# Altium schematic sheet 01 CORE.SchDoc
size 513 x 386 mm
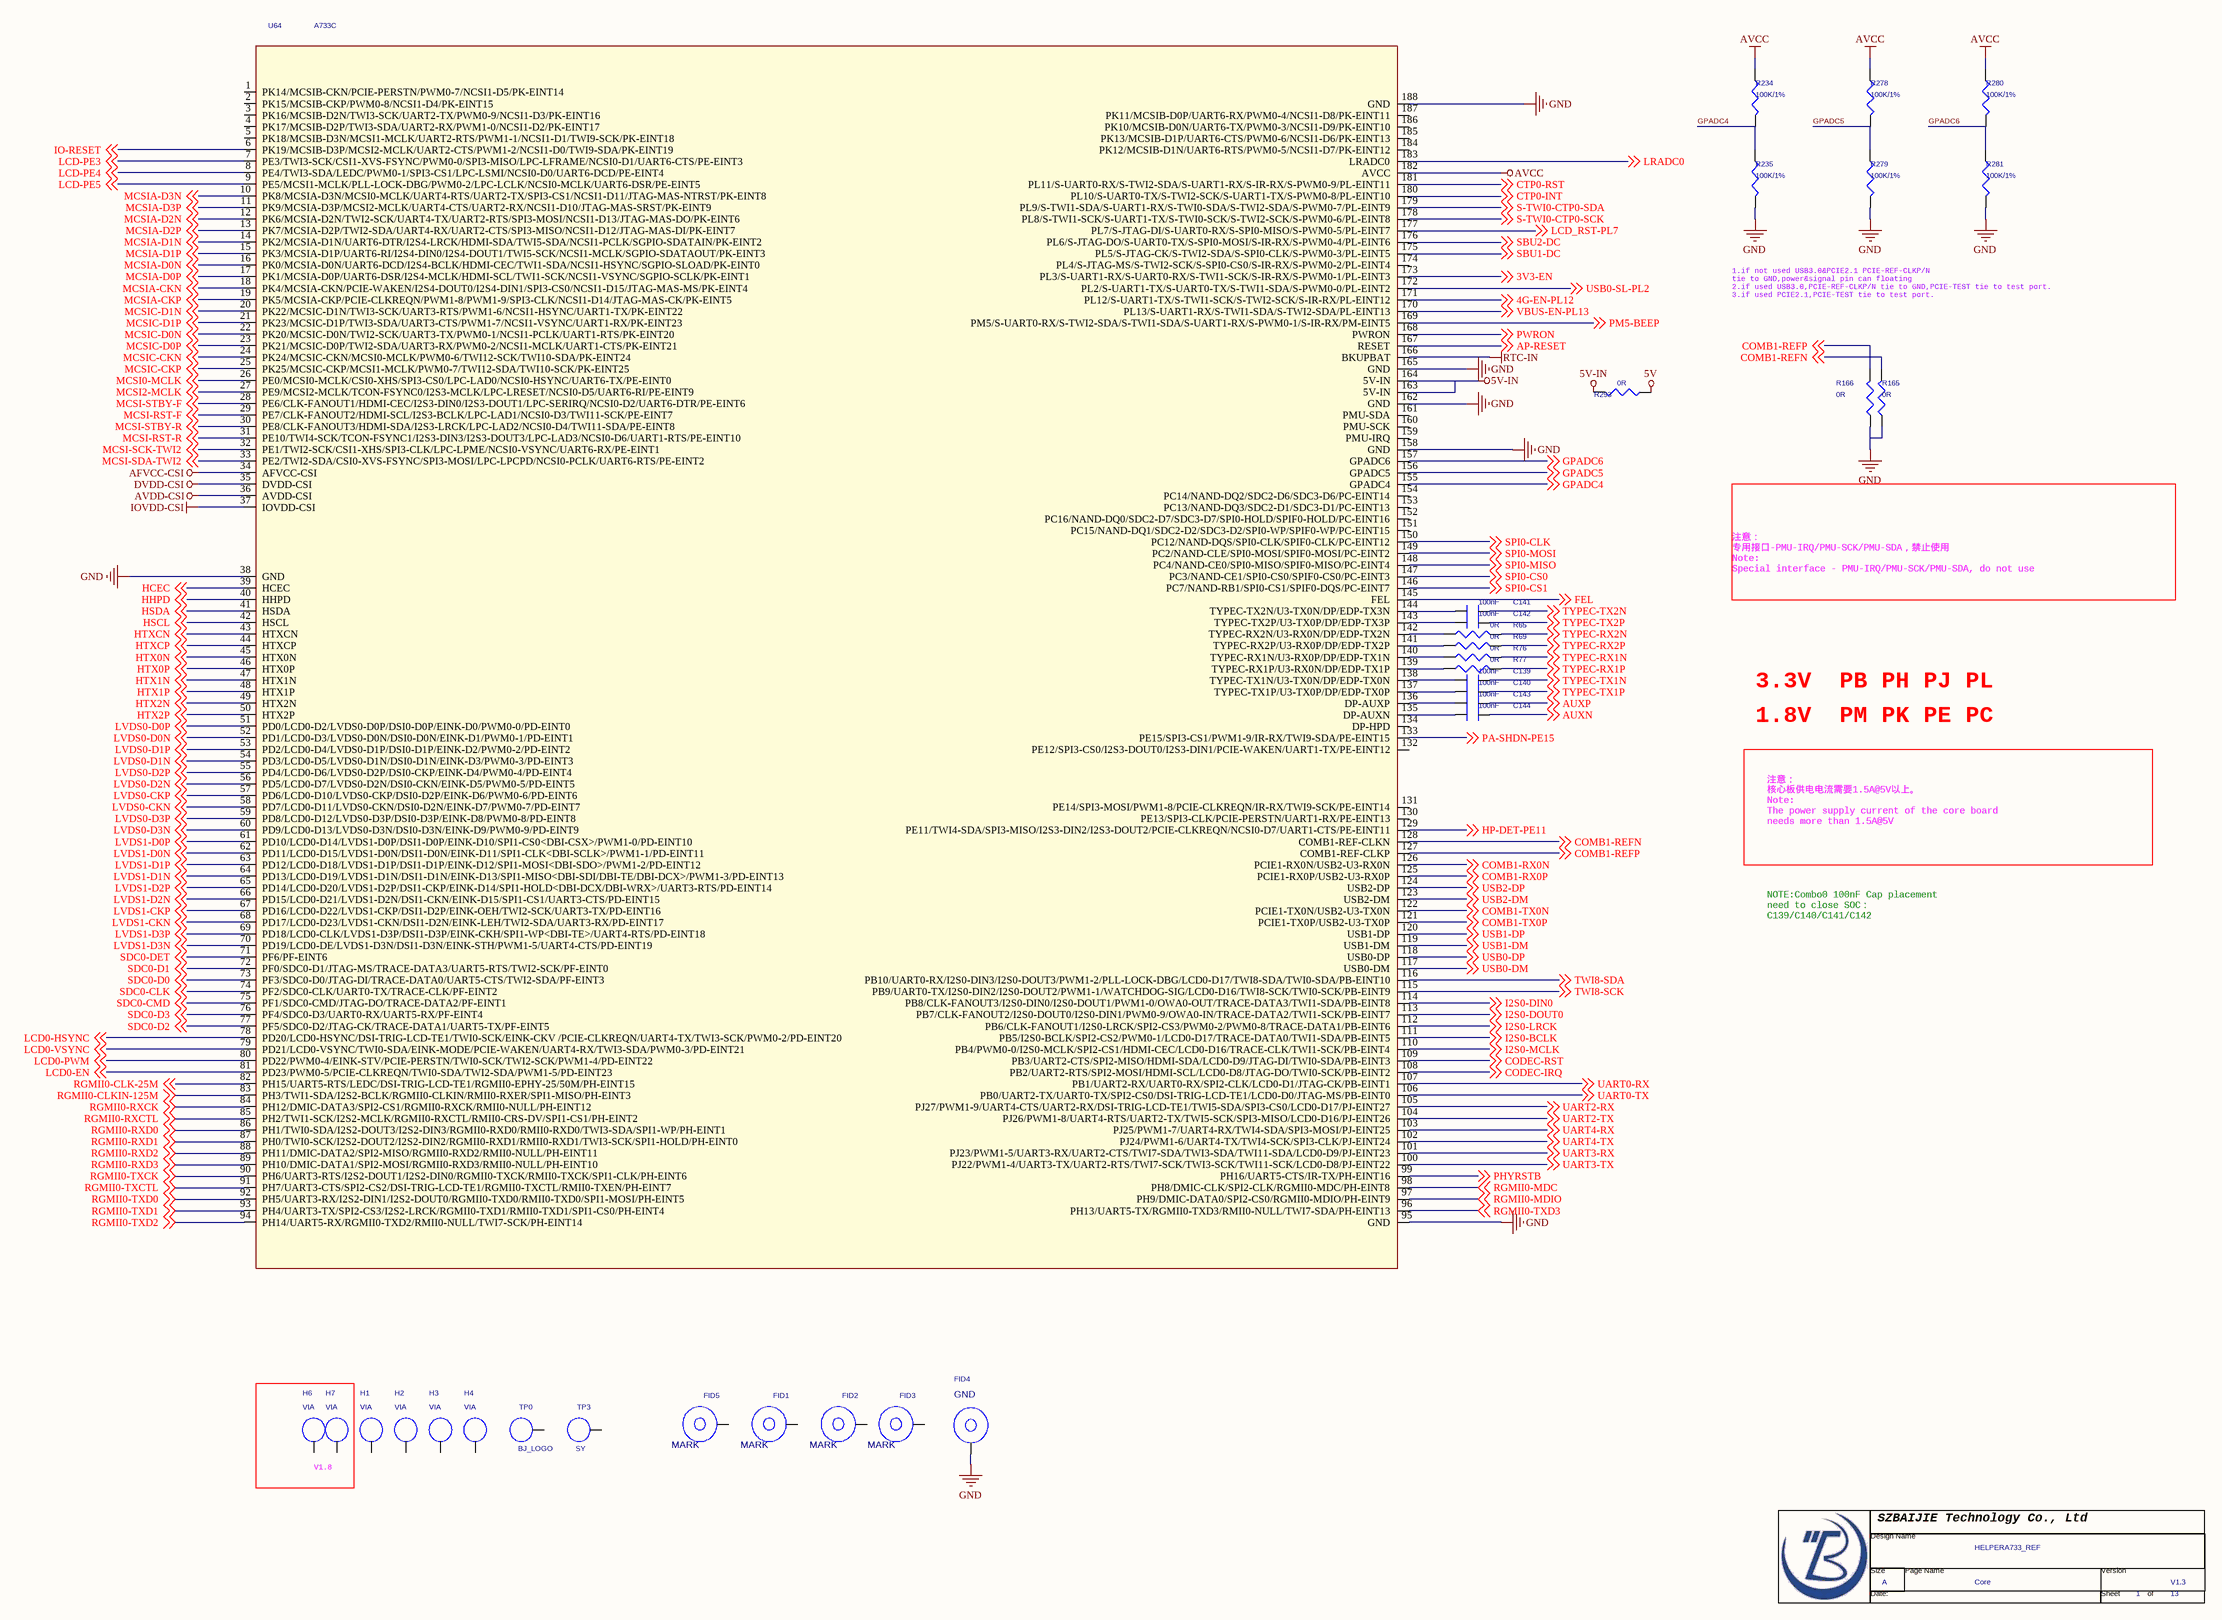
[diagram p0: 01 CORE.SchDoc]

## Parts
*  Page Count: 13  Page Number: 1  Page Size: A  Title: HELPERA733_REF  RevCode: V1.3  Doc: Core  (hidden comment: TitleBlock0-BJ)  (graphical)
C139  100nF  [C0402]
C140  100nF  [C0402]
C141  100nF  [C0402]
C142  100nF  [C0402]
C143  100nF  [C0402]
C144  100nF  [C0402]
FID1  MARK  [FIDICALMARK]
FID2  MARK  [FIDICALMARK]
FID3  MARK  [FIDICALMARK]
FID4  GND  [FIDICALMARK]
FID5  MARK  [FIDICALMARK]
H1  VIA  [DV]
H2  VIA  [DV]
H3  VIA  [DV]
H4  VIA  [DV]
H6  VIA  [DV]
H7  VIA  [DV]
R65  0R  [R0402]
R69  0R  [R0402]
R76  0R  [R0402]
R77  0R  [R0402]
R165  0R  [R0402]
R166  0R  [R0402]
R234  100K/1%  [0805]
R235  100K/1%  [0805]
R278  100K/1%  [0805]
R279  100K/1%  [0805]
R280  100K/1%  [0805]
R281  100K/1%  [0805]
R293  0R  [R0805]
TP0  BJ_LOGO  [BJ_LOGO]
TP3  SY  [6X6]
U64  A733C  [HELPERA733D-1]

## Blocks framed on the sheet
V1.8: H6 H7

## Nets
5V: R293.1
5V-IN: R293.2 U64.163(5V-IN) U64.164(5V-IN)
AFVCC-CSI: U64.34(AFVCC-CSI)
AVCC: R234.1 R278.1 R280.1 U64.182(AVCC)
AVDD-CSI: U64.36(AVDD-CSI)
DVDD-CSI: U64.35(DVDD-CSI)
GND: FID4.1(TP) R165.1 R166.1 R235.2 R279.2 R281.2 U64.38(GND) U64.95(GND) U64.158(GND) U64.162(GND) U64.165(GND) U64.188(GND)
IOVDD-CSI: U64.37(IOVDD-CSI)
RTC-IN: U64.166(BKUPBAT)
3V3-EN: U64.173(PL3/S-UART1-RX/S-UART0-RX/S-TWI1-SCK/S-IR-RX/S-PWM0-1/PL-EINT3) ; off-sheet 3V3-EN
4G-EN-PL12: U64.171(PL12/S-UART1-TX/S-TWI1-SCK/S-TWI2-SCK/S-IR-RX/PL-EINT12) ; off-sheet 4G-EN-PL12
AP-RESET: U64.167(RESET) ; off-sheet AP-RESET
AUXN: C144.2 ; off-sheet AUXN
AUXP: C143.2 ; off-sheet AUXP
CODEC-IRQ: U64.108(PB2/UART2-RTS/SPI2-MOSI/HDMI-SCL/LCD0-D8/JTAG-DO/TWI0-SCK/PB-EINT2) ; off-sheet CODEC-IRQ
CODEC-RST: U64.109(PB3/UART2-CTS/SPI2-MISO/HDMI-SDA/LCD0-D9/JTAG-DI/TWI0-SDA/PB-EINT3) ; off-sheet CODEC-RST
COMB1-REFN: R165.2 U64.128(COMB1-REF-CLKN) ; off-sheet COMB1-REFN
COMB1-REFP: R166.2 U64.127(COMB1-REF-CLKP) ; off-sheet COMB1-REFP
COMB1-RX0N: U64.126(PCIE1-RX0N/USB2-U3-RX0N) ; off-sheet COMB1-RX0N
COMB1-RX0P: U64.125(PCIE1-RX0P/USB2-U3-RX0P) ; off-sheet COMB1-RX0P
COMB1-TX0N: U64.122(PCIE1-TX0N/USB2-U3-TX0N) ; off-sheet COMB1-TX0N
COMB1-TX0P: U64.121(PCIE1-TX0P/USB2-U3-TX0P) ; off-sheet COMB1-TX0P
CTP0-INT: U64.180(PL10/S-UART0-TX/S-TWI2-SCK/S-UART1-TX/S-PWM0-8/PL-EINT10) ; off-sheet CTP0-INT
CTP0-RST: U64.181(PL11/S-UART0-RX/S-TWI2-SDA/S-UART1-RX/S-IR-RX/S-PWM0-9/PL-EINT11) ; off-sheet CTP0-RST
FEL: U64.145(FEL) ; off-sheet FEL
GPADC4: R234.2 R235.1 U64.155(GPADC4) ; off-sheet GPADC4
GPADC5: R278.2 R279.1 U64.156(GPADC5) ; off-sheet GPADC5
GPADC6: R280.2 R281.1 U64.157(GPADC6) ; off-sheet GPADC6
HCEC: U64.39(HCEC) ; off-sheet HCEC
HHPD: U64.40(HHPD) ; off-sheet HHPD
HP-DET-PE11: U64.129(PE11/TWI4-SDA/SPI3-MISO/I2S3-DIN2/I2S3-DOUT2/PCIE-CLKREQN/NCSI0-D7/UART1-CTS/PE-EINT11) ; off-sheet HP-DET-PE11
HSCL: U64.42(HSCL) ; off-sheet HSCL
HSDA: U64.41(HSDA) ; off-sheet HSDA
HTX0N: U64.45(HTX0N) ; off-sheet HTX0N
HTX0P: U64.46(HTX0P) ; off-sheet HTX0P
HTX1N: U64.47(HTX1N) ; off-sheet HTX1N
HTX1P: U64.48(HTX1P) ; off-sheet HTX1P
HTX2N: U64.49(HTX2N) ; off-sheet HTX2N
HTX2P: U64.50(HTX2P) ; off-sheet HTX2P
HTXCN: U64.43(HTXCN) ; off-sheet HTXCN
HTXCP: U64.44(HTXCP) ; off-sheet HTXCP
I2S0-BCLK: U64.111(PB5/I2S0-BCLK/SPI2-CS2/PWM0-1/LCD0-D17/TRACE-DATA0/TWI1-SDA/PB-EINT5) ; off-sheet I2S0-BCLK
I2S0-DIN0: U64.114(PB8/CLK-FANOUT3/I2S0-DIN0/I2S0-DOUT1/PWM1-0/OWA0-OUT/TRACE-DATA3/TWI1-SDA/PB-EINT8) ; off-sheet I2S0-DIN0
I2S0-DOUT0: U64.113(PB7/CLK-FANOUT2/I2S0-DOUT0/I2S0-DIN1/PWM0-9/OWA0-IN/TRACE-DATA2/TWI1-SCK/PB-EINT7) ; off-sheet I2S0-DOUT0
I2S0-LRCK: U64.112(PB6/CLK-FANOUT1/I2S0-LRCK/SPI2-CS3/PWM0-2/PWM0-8/TRACE-DATA1/PB-EINT6) ; off-sheet I2S0-LRCK
I2S0-MCLK: U64.110(PB4/PWM0-0/I2S0-MCLK/SPI2-CS1/HDMI-CEC/LCD0-D16/TRACE-CLK/TWI1-SCK/PB-EINT4) ; off-sheet I2S0-MCLK
IO-RESET: U64.6(PK19/MCSIB-D3P/MCSI2-MCLK/UART2-CTS/PWM1-2/NCSI1-D0/TWI9-SDA/PK-EINT19) ; off-sheet IO-RESET
LCD0-EN: U64.81(PD23/PWM0-5/PCIE-CLKREQN/TWI0-SDA/TWI2-SDA/PWM1-5/PD-EINT23) ; off-sheet LCD0-EN
LCD0-HSYNC: U64.78(PD20/LCD0-HSYNC/DSI-TRIG-LCD-TE1/TWI0-SCK/EINK-CKV_/PCIE-CLKREQN/UART4-TX/TWI3-SCK/PWM0-2/PD-EINT20) ; off-sheet LCD0-HSYNC
LCD0-PWM: U64.80(PD22/PWM0-4/EINK-STV/PCIE-PERSTN/TWI0-SCK/TWI2-SCK/PWM1-4/PD-EINT22) ; off-sheet LCD0-PWM
LCD0-VSYNC: U64.79(PD21/LCD0-VSYNC/TWI0-SDA/EINK-MODE/PCIE-WAKEN/UART4-RX/TWI3-SDA/PWM0-3/PD-EINT21) ; off-sheet LCD0-VSYNC
LCD-PE3: U64.7(PE3/TWI3-SCK/CSI1-XVS-FSYNC/PWM0-0/SPI3-MISO/LPC-LFRAME/NCSI0-D1/UART6-CTS/PE-EINT3) ; off-sheet LCD-PE3
LCD-PE4: U64.8(PE4/TWI3-SDA/LEDC/PWM0-1/SPI3-CS1/LPC-LSMI/NCSI0-D0/UART6-DCD/PE-EINT4) ; off-sheet LCD-PE4
LCD-PE5: U64.9(PE5/MCSI1-MCLK/PLL-LOCK-DBG/PWM0-2/LPC-LCLK/NCSI0-MCLK/UART6-DSR/PE-EINT5) ; off-sheet LCD-PE5
LCD_RST-PL7: U64.177(PL7/S-JTAG-DI/S-UART0-RX/S-SPI0-MISO/S-PWM0-5/PL-EINT7) ; off-sheet LCD_RST-PL7
LRADC0: U64.183(LRADC0) ; off-sheet LRADC0
LVDS0-CKN: U64.58(PD7/LCD0-D11/LVDS0-CKN/DSI0-D2N/EINK-D7/PWM0-7/PD-EINT7) ; off-sheet LVDS0-CKN
LVDS0-CKP: U64.57(PD6/LCD0-D10/LVDS0-CKP/DSI0-D2P/EINK-D6/PWM0-6/PD-EINT6) ; off-sheet LVDS0-CKP
LVDS0-D0N: U64.52(PD1/LCD0-D3/LVDS0-D0N/DSI0-D0N/EINK-D1/PWM0-1/PD-EINT1) ; off-sheet LVDS0-D0N
LVDS0-D0P: U64.51(PD0/LCD0-D2/LVDS0-D0P/DSI0-D0P/EINK-D0/PWM0-0/PD-EINT0) ; off-sheet LVDS0-D0P
LVDS0-D1N: U64.54(PD3/LCD0-D5/LVDS0-D1N/DSI0-D1N/EINK-D3/PWM0-3/PD-EINT3) ; off-sheet LVDS0-D1N
LVDS0-D1P: U64.53(PD2/LCD0-D4/LVDS0-D1P/DSI0-D1P/EINK-D2/PWM0-2/PD-EINT2) ; off-sheet LVDS0-D1P
LVDS0-D2N: U64.56(PD5/LCD0-D7/LVDS0-D2N/DSI0-CKN/EINK-D5/PWM0-5/PD-EINT5) ; off-sheet LVDS0-D2N
LVDS0-D2P: U64.55(PD4/LCD0-D6/LVDS0-D2P/DSI0-CKP/EINK-D4/PWM0-4/PD-EINT4) ; off-sheet LVDS0-D2P
LVDS0-D3N: U64.60(PD9/LCD0-D13/LVDS0-D3N/DSI0-D3N/EINK-D9/PWM0-9/PD-EINT9) ; off-sheet LVDS0-D3N
LVDS0-D3P: U64.59(PD8/LCD0-D12/LVDS0-D3P/DSI0-D3P/EINK-D8/PWM0-8/PD-EINT8) ; off-sheet LVDS0-D3P
LVDS1-CKN: U64.68(PD17/LCD0-D23/LVDS1-CKN/DSI1-D2N/EINK-LEH/TWI2-SDA/UART3-RX/PD-EINT17) ; off-sheet LVDS1-CKN
LVDS1-CKP: U64.67(PD16/LCD0-D22/LVDS1-CKP/DSI1-D2P/EINK-OEH/TWI2-SCK/UART3-TX/PD-EINT16) ; off-sheet LVDS1-CKP
LVDS1-D0N: U64.62(PD11/LCD0-D15/LVDS1-D0N/DSI1-D0N/EINK-D11/SPI1-CLK<DBI-SCLK>/PWM1-1/PD-EINT11) ; off-sheet LVDS1-D0N
LVDS1-D0P: U64.61(PD10/LCD0-D14/LVDS1-D0P/DSI1-D0P/EINK-D10/SPI1-CS0<DBI-CSX>/PWM1-0/PD-EINT10) ; off-sheet LVDS1-D0P
LVDS1-D1N: U64.64(PD13/LCD0-D19/LVDS1-D1N/DSI1-D1N/EINK-D13/SPI1-MISO<DBI-SDI/DBI-TE/DBI-DCX>/PWM1-3/PD-EINT13) ; off-sheet LVDS1-D1N
LVDS1-D1P: U64.63(PD12/LCD0-D18/LVDS1-D1P/DSI1-D1P/EINK-D12/SPI1-MOSI<DBI-SDO>/PWM1-2/PD-EINT12) ; off-sheet LVDS1-D1P
LVDS1-D2N: U64.66(PD15/LCD0-D21/LVDS1-D2N/DSI1-CKN/EINK-D15/SPI1-CS1/UART3-CTS/PD-EINT15) ; off-sheet LVDS1-D2N
LVDS1-D2P: U64.65(PD14/LCD0-D20/LVDS1-D2P/DSI1-CKP/EINK-D14/SPI1-HOLD<DBI-DCX/DBI-WRX>/UART3-RTS/PD-EINT14) ; off-sheet LVDS1-D2P
LVDS1-D3N: U64.70(PD19/LCD0-DE/LVDS1-D3N/DSI1-D3N/EINK-STH/PWM1-5/UART4-CTS/PD-EINT19) ; off-sheet LVDS1-D3N
LVDS1-D3P: U64.69(PD18/LCD0-CLK/LVDS1-D3P/DSI1-D3P/EINK-CKH/SPI1-WP<DBI-TE>/UART4-RTS/PD-EINT18) ; off-sheet LVDS1-D3P
MCSI0-MCLK: U64.26(PE0/MCSI0-MCLK/CSI0-XHS/SPI3-CS0/LPC-LAD0/NCSI0-HSYNC/UART6-TX/PE-EINT0) ; off-sheet MCSI0-MCLK
MCSI2-MCLK: U64.27(PE9/MCSI2-MCLK/TCON-FSYNC0/I2S3-MCLK/LPC-LRESET/NCSI0-D5/UART6-RI/PE-EINT9) ; off-sheet MCSI2-MCLK
MCSI-RST-F: U64.29(PE7/CLK-FANOUT2/HDMI-SCL/I2S3-BCLK/LPC-LAD1/NCSI0-D3/TWI11-SCK/PE-EINT7) ; off-sheet MCSI-RST-F
MCSI-RST-R: U64.31(PE10/TWI4-SCK/TCON-FSYNC1/I2S3-DIN3/I2S3-DOUT3/LPC-LAD3/NCSI0-D6/UART1-RTS/PE-EINT10) ; off-sheet MCSI-RST-R
MCSI-SCK-TWI2: U64.32(PE1/TWI2-SCK/CSI1-XHS/SPI3-CLK/LPC-LPME/NCSI0-VSYNC/UART6-RX/PE-EINT1) ; off-sheet MCSI-SCK-TWI2
MCSI-SDA-TWI2: U64.33(PE2/TWI2-SDA/CSI0-XVS-FSYNC/SPI3-MOSI/LPC-LPCPD/NCSI0-PCLK/UART6-RTS/PE-EINT2) ; off-sheet MCSI-SDA-TWI2
MCSI-STBY-F: U64.28(PE6/CLK-FANOUT1/HDMI-CEC/I2S3-DIN0/I2S3-DOUT1/LPC-SERIRQ/NCSI0-D2/UART6-DTR/PE-EINT6) ; off-sheet MCSI-STBY-F
MCSI-STBY-R: U64.30(PE8/CLK-FANOUT3/HDMI-SDA/I2S3-LRCK/LPC-LAD2/NCSI0-D4/TWI11-SDA/PE-EINT8) ; off-sheet MCSI-STBY-R
MCSIA-CKN: U64.18(PK4/MCSIA-CKN/PCIE-WAKEN/I2S4-DOUT0/I2S4-DIN1/SPI3-CS0/NCSI1-D15/JTAG-MAS-MS/PK-EINT4) ; off-sheet MCSIA-CKN
MCSIA-CKP: U64.19(PK5/MCSIA-CKP/PCIE-CLKREQN/PWM1-8/PWM1-9/SPI3-CLK/NCSI1-D14/JTAG-MAS-CK/PK-EINT5) ; off-sheet MCSIA-CKP
MCSIA-D0N: U64.16(PK0/MCSIA-D0N/UART6-DCD/I2S4-BCLK/HDMI-CEC/TWI1-SDA/NCSI1-HSYNC/SGPIO-SLOAD/PK-EINT0) ; off-sheet MCSIA-D0N
MCSIA-D0P: U64.17(PK1/MCSIA-D0P/UART6-DSR/I2S4-MCLK/HDMI-SCL/TWI1-SCK/NCSI1-VSYNC/SGPIO-SCLK/PK-EINT1) ; off-sheet MCSIA-D0P
MCSIA-D1N: U64.14(PK2/MCSIA-D1N/UART6-DTR/I2S4-LRCK/HDMI-SDA/TWI5-SDA/NCSI1-PCLK/SGPIO-SDATAIN/PK-EINT2) ; off-sheet MCSIA-D1N
MCSIA-D1P: U64.15(PK3/MCSIA-D1P/UART6-RI/I2S4-DIN0/I2S4-DOUT1/TWI5-SCK/NCSI1-MCLK/SGPIO-SDATAOUT/PK-EINT3) ; off-sheet MCSIA-D1P
MCSIA-D2N: U64.12(PK6/MCSIA-D2N/TWI2-SCK/UART4-TX/UART2-RTS/SPI3-MOSI/NCSI1-D13/JTAG-MAS-DO/PK-EINT6) ; off-sheet MCSIA-D2N
MCSIA-D2P: U64.13(PK7/MCSIA-D2P/TWI2-SDA/UART4-RX/UART2-CTS/SPI3-MISO/NCSI1-D12/JTAG-MAS-DI/PK-EINT7) ; off-sheet MCSIA-D2P
MCSIA-D3N: U64.10(PK8/MCSIA-D3N/MCSI0-MCLK/UART4-RTS/UART2-TX/SPI3-CS1/NCSI1-D11/JTAG-MAS-NTRST/PK-EINT8) ; off-sheet MCSIA-D3N
MCSIA-D3P: U64.11(PK9/MCSIA-D3P/MCSI2-MCLK/UART4-CTS/UART2-RX/NCSI1-D10/JTAG-MAS-SRST/PK-EINT9) ; off-sheet MCSIA-D3P
MCSIC-CKN: U64.24(PK24/MCSIC-CKN/MCSI0-MCLK/PWM0-6/TWI12-SCK/TWI10-SDA/PK-EINT24) ; off-sheet MCSIC-CKN
MCSIC-CKP: U64.25(PK25/MCSIC-CKP/MCSI1-MCLK/PWM0-7/TWI12-SDA/TWI10-SCK/PK-EINT25) ; off-sheet MCSIC-CKP
MCSIC-D0N: U64.22(PK20/MCSIC-D0N/TWI2-SCK/UART3-TX/PWM0-1/NCSI1-PCLK/UART1-RTS/PK-EINT20) ; off-sheet MCSIC-D0N
MCSIC-D0P: U64.23(PK21/MCSIC-D0P/TWI2-SDA/UART3-RX/PWM0-2/NCSI1-MCLK/UART1-CTS/PK-EINT21) ; off-sheet MCSIC-D0P
MCSIC-D1N: U64.20(PK22/MCSIC-D1N/TWI3-SCK/UART3-RTS/PWM1-6/NCSI1-HSYNC/UART1-TX/PK-EINT22) ; off-sheet MCSIC-D1N
MCSIC-D1P: U64.21(PK23/MCSIC-D1P/TWI3-SDA/UART3-CTS/PWM1-7/NCSI1-VSYNC/UART1-RX/PK-EINT23) ; off-sheet MCSIC-D1P
PA-SHDN-PE15: U64.133(PE15/SPI3-CS1/PWM1-9/IR-RX/TWI9-SDA/PE-EINT15) ; off-sheet PA-SHDN-PE15
PHYRSTB: U64.99(PH16/UART5-CTS/IR-TX/PH-EINT16) ; off-sheet PHYRSTB
PM5-BEEP: U64.169(PM5/S-UART0-RX/S-TWI2-SDA/S-TWI1-SDA/S-UART1-RX/S-PWM0-1/S-IR-RX/PM-EINT5) ; off-sheet PM5-BEEP
PWRON: U64.168(PWRON) ; off-sheet PWRON
RGMII0-CLK-25M: U64.82(PH15/UART5-RTS/LEDC/DSI-TRIG-LCD-TE1/RGMII0-EPHY-25/50M/PH-EINT15) ; off-sheet RGMII0-CLK-25M
RGMII0-CLKIN-125M: U64.83(PH3/TWI1-SDA/I2S2-BCLK/RGMII0-CLKIN/RMII0-RXER/SPI1-MISO/PH-EINT3) ; off-sheet RGMII0-CLKIN-125M
RGMII0-MDC: U64.98(PH8/DMIC-CLK/SPI2-CLK/RGMII0-MDC/PH-EINT8) ; off-sheet RGMII0-MDC
RGMII0-MDIO: U64.97(PH9/DMIC-DATA0/SPI2-CS0/RGMII0-MDIO/PH-EINT9) ; off-sheet RGMII0-MDIO
RGMII0-RXCK: U64.84(PH12/DMIC-DATA3/SPI2-CS1/RGMII0-RXCK/RMII0-NULL/PH-EINT12) ; off-sheet RGMII0-RXCK
RGMII0-RXCTL: U64.85(PH2/TWI1-SCK/I2S2-MCLK/RGMII0-RXCTL/RMII0-CRS-DV/SPI1-CS1/PH-EINT2) ; off-sheet RGMII0-RXCTL
RGMII0-RXD0: U64.86(PH1/TWI0-SDA/I2S2-DOUT3/I2S2-DIN3/RGMII0-RXD0/RMII0-RXD0/TWI3-SDA/SPI1-WP/PH-EINT1) ; off-sheet RGMII0-RXD0
RGMII0-RXD1: U64.87(PH0/TWI0-SCK/I2S2-DOUT2/I2S2-DIN2/RGMII0-RXD1/RMII0-RXD1/TWI3-SCK/SPI1-HOLD/PH-EINT0) ; off-sheet RGMII0-RXD1
RGMII0-RXD2: U64.88(PH11/DMIC-DATA2/SPI2-MISO/RGMII0-RXD2/RMII0-NULL/PH-EINT11) ; off-sheet RGMII0-RXD2
RGMII0-RXD3: U64.89(PH10/DMIC-DATA1/SPI2-MOSI/RGMII0-RXD3/RMII0-NULL/PH-EINT10) ; off-sheet RGMII0-RXD3
RGMII0-TXCK: U64.90(PH6/UART3-RTS/I2S2-DOUT1/I2S2-DIN0/RGMII0-TXCK/RMII0-TXCK/SPI1-CLK/PH-EINT6) ; off-sheet RGMII0-TXCK
RGMII0-TXCTL: U64.91(PH7/UART3-CTS/SPI2-CS2/DSI-TRIG-LCD-TE1/RGMII0-TXCTL/RMII0-TXEN/PH-EINT7) ; off-sheet RGMII0-TXCTL
RGMII0-TXD0: U64.92(PH5/UART3-RX/I2S2-DIN1/I2S2-DOUT0/RGMII0-TXD0/RMII0-TXD0/SPI1-MOSI/PH-EINT5) ; off-sheet RGMII0-TXD0
RGMII0-TXD1: U64.93(PH4/UART3-TX/SPI2-CS3/I2S2-LRCK/RGMII0-TXD1/RMII0-TXD1/SPI1-CS0/PH-EINT4) ; off-sheet RGMII0-TXD1
RGMII0-TXD2: U64.94(PH14/UART5-RX/RGMII0-TXD2/RMII0-NULL/TWI7-SCK/PH-EINT14) ; off-sheet RGMII0-TXD2
RGMII0-TXD3: U64.96(PH13/UART5-TX/RGMII0-TXD3/RMII0-NULL/TWI7-SDA/PH-EINT13) ; off-sheet RGMII0-TXD3
S-TWI0-CTP0-SCK: U64.178(PL8/S-TWI1-SCK/S-UART1-TX/S-TWI0-SCK/S-TWI2-SCK/S-PWM0-6/PL-EINT8) ; off-sheet S-TWI0-CTP0-SCK
S-TWI0-CTP0-SDA: U64.179(PL9/S-TWI1-SDA/S-UART1-RX/S-TWI0-SDA/S-TWI2-SDA/S-PWM0-7/PL-EINT9) ; off-sheet S-TWI0-CTP0-SDA
SBU1-DC: U64.175(PL5/S-JTAG-CK/S-TWI2-SDA/S-SPI0-CLK/S-PWM0-3/PL-EINT5) ; off-sheet SBU1-DC
SBU2-DC: U64.176(PL6/S-JTAG-DO/S-UART0-TX/S-SPI0-MOSI/S-IR-RX/S-PWM0-4/PL-EINT6) ; off-sheet SBU2-DC
SDC0-CLK: U64.74(PF2/SDC0-CLK/UART0-TX/TRACE-CLK/PF-EINT2) ; off-sheet SDC0-CLK
SDC0-CMD: U64.75(PF1/SDC0-CMD/JTAG-DO/TRACE-DATA2/PF-EINT1) ; off-sheet SDC0-CMD
SDC0-D0: U64.73(PF3/SDC0-D0/JTAG-DI/TRACE-DATA0/UART5-CTS/TWI2-SDA/PF-EINT3) ; off-sheet SDC0-D0
SDC0-D1: U64.72(PF0/SDC0-D1/JTAG-MS/TRACE-DATA3/UART5-RTS/TWI2-SCK/PF-EINT0) ; off-sheet SDC0-D1
SDC0-D2: U64.77(PF5/SDC0-D2/JTAG-CK/TRACE-DATA1/UART5-TX/PF-EINT5) ; off-sheet SDC0-D2
SDC0-D3: U64.76(PF4/SDC0-D3/UART0-RX/UART5-RX/PF-EINT4) ; off-sheet SDC0-D3
SDC0-DET: U64.71(PF6/PF-EINT6) ; off-sheet SDC0-DET
SPI0-CLK: U64.150(PC12/NAND-DQS/SPI0-CLK/SPIF0-CLK/PC-EINT12) ; off-sheet SPI0-CLK
SPI0-CS0: U64.147(PC3/NAND-CE1/SPI0-CS0/SPIF0-CS0/PC-EINT3) ; off-sheet SPI0-CS0
SPI0-CS1: U64.146(PC7/NAND-RB1/SPI0-CS1/SPIF0-DQS/PC-EINT7) ; off-sheet SPI0-CS1
SPI0-MISO: U64.148(PC4/NAND-CE0/SPI0-MISO/SPIF0-MISO/PC-EINT4) ; off-sheet SPI0-MISO
SPI0-MOSI: U64.149(PC2/NAND-CLE/SPI0-MOSI/SPIF0-MOSI/PC-EINT2) ; off-sheet SPI0-MOSI
TWI8-SCK: U64.115(PB9/UART0-TX/I2S0-DIN2/I2S0-DOUT2/PWM1-1/WATCHDOG-SIG/LCD0-D16/TWI8-SCK/TWI0-SCK/PB-EINT9) ; off-sheet TWI8-SCK
TWI8-SDA: U64.116(PB10/UART0-RX/I2S0-DIN3/I2S0-DOUT3/PWM1-2/PLL-LOCK-DBG/LCD0-D17/TWI8-SDA/TWI0-SDA/PB-EINT10) ; off-sheet TWI8-SDA
TYPEC-RX1N: R76.2 ; off-sheet TYPEC-RX1N
TYPEC-RX1P: R77.2 ; off-sheet TYPEC-RX1P
TYPEC-RX2N: R65.2 ; off-sheet TYPEC-RX2N
TYPEC-RX2P: R69.2 ; off-sheet TYPEC-RX2P
TYPEC-TX1N: C139.2 ; off-sheet TYPEC-TX1N
TYPEC-TX1P: C140.2 ; off-sheet TYPEC-TX1P
TYPEC-TX2N: C141.2 ; off-sheet TYPEC-TX2N
TYPEC-TX2P: C142.2 ; off-sheet TYPEC-TX2P
UART0-RX: U64.107(PB1/UART2-RX/UART0-RX/SPI2-CLK/LCD0-D1/JTAG-CK/PB-EINT1) ; off-sheet UART0-RX
UART0-TX: U64.106(PB0/UART2-TX/UART0-TX/SPI2-CS0/DSI-TRIG-LCD-TE1/LCD0-D0/JTAG-MS/PB-EINT0) ; off-sheet UART0-TX
UART2-RX: U64.105(PJ27/PWM1-9/UART4-CTS/UART2-RX/DSI-TRIG-LCD-TE1/TWI5-SDA/SPI3-CS0/LCD0-D17/PJ-EINT27) ; off-sheet UART2-RX
UART2-TX: U64.104(PJ26/PWM1-8/UART4-RTS/UART2-TX/TWI5-SCK/SPI3-MISO/LCD0-D16/PJ-EINT26) ; off-sheet UART2-TX
UART3-RX: U64.101(PJ23/PWM1-5/UART3-RX/UART2-CTS/TWI7-SDA/TWI3-SDA/TWI11-SDA/LCD0-D9/PJ-EINT23) ; off-sheet UART3-RX
UART3-TX: U64.100(PJ22/PWM1-4/UART3-TX/UART2-RTS/TWI7-SCK/TWI3-SCK/TWI11-SCK/LCD0-D8/PJ-EINT22) ; off-sheet UART3-TX
UART4-RX: U64.103(PJ25/PWM1-7/UART4-RX/TWI4-SDA/SPI3-MOSI/PJ-EINT25) ; off-sheet UART4-RX
UART4-TX: U64.102(PJ24/PWM1-6/UART4-TX/TWI4-SCK/SPI3-CLK/PJ-EINT24) ; off-sheet UART4-TX
USB0-DM: U64.117(USB0-DM) ; off-sheet USB0-DM
USB0-DP: U64.118(USB0-DP) ; off-sheet USB0-DP
USB0-SL-PL2: U64.172(PL2/S-UART1-TX/S-UART0-TX/S-TWI1-SDA/S-PWM0-0/PL-EINT2) ; off-sheet USB0-SL-PL2
USB1-DM: U64.119(USB1-DM) ; off-sheet USB1-DM
USB1-DP: U64.120(USB1-DP) ; off-sheet USB1-DP
USB2-DM: U64.123(USB2-DM) ; off-sheet USB2-DM
USB2-DP: U64.124(USB2-DP) ; off-sheet USB2-DP
VBUS-EN-PL13: U64.170(PL13/S-UART1-RX/S-TWI1-SDA/S-TWI2-SDA/PL-EINT13) ; off-sheet VBUS-EN-PL13
NetC139_1: C139.1 U64.138(TYPEC-TX1N/U3-TX0N/DP/EDP-TX0N)
NetC140_1: C140.1 U64.137(TYPEC-TX1P/U3-TX0P/DP/EDP-TX0P)
NetC141_1: C141.1 U64.144(TYPEC-TX2N/U3-TX0N/DP/EDP-TX3N)
NetC142_1: C142.1 U64.143(TYPEC-TX2P/U3-TX0P/DP/EDP-TX3P)
NetC143_1: C143.1 U64.136(DP-AUXP)
NetC144_1: C144.1 U64.135(DP-AUXN)
NetR65_1: R65.1 U64.142(TYPEC-RX2N/U3-RX0N/DP/EDP-TX2N)
NetR69_1: R69.1 U64.141(TYPEC-RX2P/U3-RX0P/DP/EDP-TX2P)
NetR76_1: R76.1 U64.140(TYPEC-RX1N/U3-RX0P/DP/EDP-TX1N)
NetR77_1: R77.1 U64.139(TYPEC-RX1P/U3-RX0N/DP/EDP-TX1P)

Not connected (* = marked no-connect by the designer): FID1 1(TP); FID2 1(TP); FID3 1(TP); FID5 1(TP); H1 1(TP); H2 1(TP); H3 1(TP); H4 1(TP); H6 1(TP); H7 1(TP); TP0 1(TP); TP3 1(TP); U64 1(PK14/MCSIB-CKN/PCIE-PERSTN/PWM0-7/NCSI1-D5/PK-EINT14) 2(PK15/MCSIB-CKP/PWM0-8/NCSI1-D4/PK-EINT15) 3(PK16/MCSIB-D2N/TWI3-SCK/UART2-TX/PWM0-9/NCSI1-D3/PK-EINT16) 4(PK17/MCSIB-D2P/TWI3-SDA/UART2-RX/PWM1-0/NCSI1-D2/PK-EINT17) 5(PK18/MCSIB-D3N/MCSI1-MCLK/UART2-RTS/PWM1-1/NCSI1-D1/TWI9-SCK/PK-EINT18) 130(PE13/SPI3-CLK/PCIE-PERSTN/UART1-RX/PE-EINT13) 131(PE14/SPI3-MOSI/PWM1-8/PCIE-CLKREQN/IR-RX/TWI9-SCK/PE-EINT14) 132(PE12/SPI3-CS0/I2S3-DOUT0/I2S3-DIN1/PCIE-WAKEN/UART1-TX/PE-EINT12) 134(DP-HPD) 151(PC15/NAND-DQ1/SDC2-D2/SDC3-D2/SPI0-WP/SPIF0-WP/PC-EINT15) 152(PC16/NAND-DQ0/SDC2-D7/SDC3-D7/SPI0-HOLD/SPIF0-HOLD/PC-EINT16) 153(PC13/NAND-DQ3/SDC2-D1/SDC3-D1/PC-EINT13) 154(PC14/NAND-DQ2/SDC2-D6/SDC3-D6/PC-EINT14) 159(PMU-IRQ) 160(PMU-SCK) 161(PMU-SDA) 174(PL4/S-JTAG-MS/S-TWI2-SCK/S-SPI0-CS0/S-IR-RX/S-PWM0-2/PL-EINT4) 184(PK12/MCSIB-D1N/UART6-RTS/PWM0-5/NCSI1-D7/PK-EINT12) 185(PK13/MCSIB-D1P/UART6-CTS/PWM0-6/NCSI1-D6/PK-EINT13) 186(PK10/MCSIB-D0N/UART6-TX/PWM0-3/NCSI1-D9/PK-EINT10) 187(PK11/MCSIB-D0P/UART6-RX/PWM0-4/NCSI1-D8/PK-EINT11)

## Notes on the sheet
- 1.if not used USB3.0&PCIE2.1 PCIE-REF-CLKP/N
  tie to GND,power&signal pin can floating
  2.if used USB3.0,PCIE-REF-CLKP/N tie to GND,PCIE-TEST tie to test port.
  3.if used PCIE2.1,PCIE-TEST tie to test port.
- 注意：
  专用接口-PMU-IRQ/PMU-SCK/PMU-SDA，禁止使用
  Note:
  Special interface - PMU-IRQ/PMU-SCK/PMU-SDA, do not use
- 3.3V  PB PH PJ PL
- 1.8V  PM PK PE PC
- 注意：
  核心板供电电流需要1.5A@5V以上。
  Note:
  The power supply current of the core board
  needs more than 1.5A@5V
- NOTE:Combo0 100nF Cap placement
  need to close SOC：
  C139/C140/C141/C142

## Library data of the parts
C139-C144 = C-C0402_Dup1: Parameter: C0402-X5R
FID1-FID5 = T POINT R_2: FIDUCAL MARK; COMPONENT_WEIGHT: 30
H1-H4 H6 H7 = T POINT R_1: HOLE
R65 R69 R76 R77 = R-R0402-1%
R165 R166 R293 = R_Dup5
R234 R235 R278-R281 = R1 0805
TP0 TP3 = T POINT R_1
U64 = AO4409_18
